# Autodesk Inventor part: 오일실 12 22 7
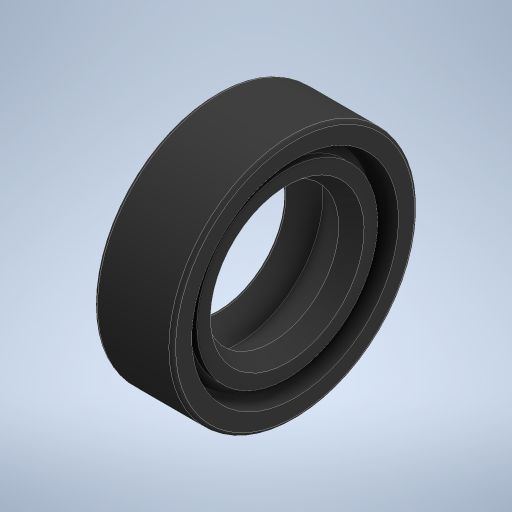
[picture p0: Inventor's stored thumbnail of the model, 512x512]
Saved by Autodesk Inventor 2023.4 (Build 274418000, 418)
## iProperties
Created: 2024-05
Part Number: 오일실 12 22 7
Material: 고무
Description: 오일-실
Document SubType Name: Modeling
Designer: EDU-001
Density: 0.93 g/cm^3
Appearance: 기본값
Author: jhkim
Sending System: Autodesk Inventor 2025
Preprocessor: ST-DEVELOPER v20
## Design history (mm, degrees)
node "오일실 12 22 71"
node "솔리드1"
body "Solid1"
